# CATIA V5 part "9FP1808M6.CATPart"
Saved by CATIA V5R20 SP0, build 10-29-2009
Part number: 9FP1808M6
Revision: ANY
Definition: UNKNOWN
Nomenclature: 9FP1808M6
Source: Unknown
Bounding box of the stored display mesh (mm): x -8.9 to 8.9, y 0 to 8, z -8.9 to 8.9
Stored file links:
  C:\Users\Utente\Desktop\IO LAVORO\3D X SITO CF\CUMSA\3D files PW\pw101430\pw101430_ejection\9FP1808M6.CATPart
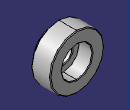
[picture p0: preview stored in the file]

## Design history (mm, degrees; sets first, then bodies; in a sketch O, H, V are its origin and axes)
Body1 "Chaflán1" (main body)
  Solid1: solid without history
